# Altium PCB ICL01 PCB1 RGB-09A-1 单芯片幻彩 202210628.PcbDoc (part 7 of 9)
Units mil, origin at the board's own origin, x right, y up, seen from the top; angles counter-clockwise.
Board outline 17436.43 x 6581.89 mil, 2 copper layers (Top Layer, Bottom Layer), stack 65.792 mil thick; 425 components, 516 nets, 1625 pads, 2772 vias.
Unrouted connection lines stored in the file: 1.
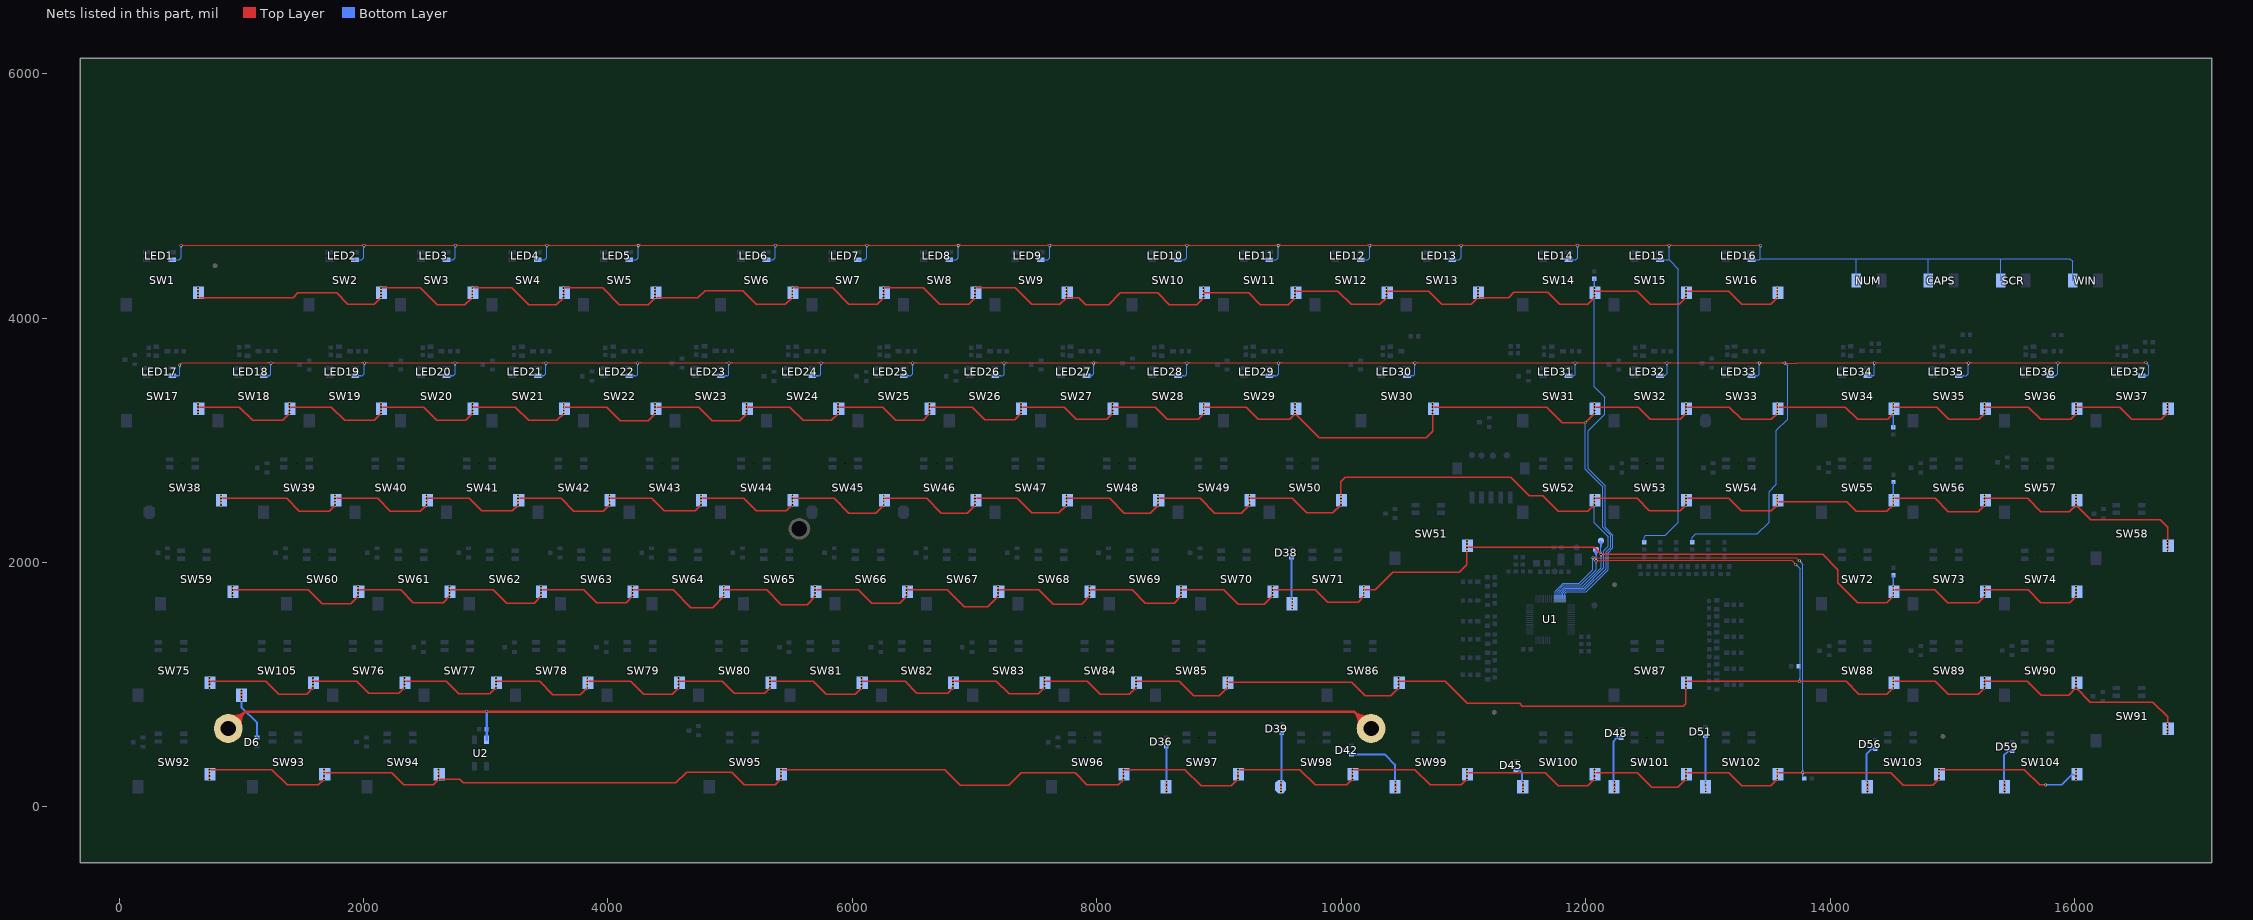
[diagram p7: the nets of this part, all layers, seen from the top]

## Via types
v1: diameter 23.62, hole 15.75, Top Layer to Bottom Layer, tented both sides, 2766 vias
v2: diameter 19.68, hole 11.81, Top Layer to Bottom Layer, tented both sides, 6 vias

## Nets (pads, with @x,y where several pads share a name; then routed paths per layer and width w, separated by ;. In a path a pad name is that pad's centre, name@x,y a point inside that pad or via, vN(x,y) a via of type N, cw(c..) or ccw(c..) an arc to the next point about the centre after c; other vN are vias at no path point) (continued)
NetSW97_2: D36.K2 SW97.2 | length 368.1
  Top Layer w15.75: v1(8568.65,206.14) v1(8568.65,179.47) v1(8568.65,152.81) 8568.65,128.11 v1@8570.62,126.14
  Bottom Layer w15.75: SW97.2@8569.36,206.14 D36.K2@8569.36,493.41
  other v1: 8568.65,126.14
NetSW98_2: D39.K2 SW98.2 | length 483.3
  Top Layer w15.75: v1(9505.66,126.14) v1(9505.66,152.81) v1(9505.66,179.47) v1(9505.66,206.14)
  Bottom Layer w15.75: SW98.2@9512.53,199.27 D39.K2@9512.53,602.59
NetSW99_2: D42.K2 SW99.2 | length 611.3
  Top Layer w15.75: v1@10440.7,126.14 10442.67,128.11 v1(10442.67,152.81) v1(10442.67,179.47) v1(10442.67,206.14)
  Bottom Layer w15.75: D42.K2@10083,427.67 10358.43,427.67 10439.44,346.66 SW99.2@10439.44,206.14
  other v1: 10442.67,126.14
NetSW100_2: D45.K2 SW100.2 | length 206.4
  Top Layer w15.75: v1@11485.98,133.03 v1(11485.98,152.81) v1(11485.98,179.47) v1(11485.98,206.14)
  Bottom Layer w15.75: D45.K2@11429.12,302.13 11458.31,302.13 11477.83,282.61 SW100.2@11477.83,206.14
  other v1: 11485.98,126.14
NetSW101_2: D48.K2 SW101.2 | length 476.8
  Top Layer w15.75: v1@12234.01,133.03 v1(12234.01,152.81) v1(12234.01,179.47) v1(12234.01,206.14)
  Bottom Layer w15.75: SW101.2@12225.86,206.14 12225.86,534.59 12255.71,564.45 D48.K2@12288.72,564.45
  other v1: 12234.01,126.14
NetSW102_2: D51.K2 SW102.2 | length 432.3
  Top Layer w15.75: v1@12982.04,133.03 v1(12982.04,152.81)
  Bottom Layer w15.75: D51.K2@12979.64,578.19 12980.78,577.06 SW102.2@12980.78,166.14
  other v1: 12982.04,126.14 12982.04,179.47 12982.04,206.14
NetSW103_2: D56.K2 SW103.2 | length 389.9
  Top Layer w15.75: v1@14304.87,131.06 v1(14304.87,152.81) v1(14304.87,179.47) v1(14304.87,206.14)
  Bottom Layer w15.75: SW103.2@14298.69,206.14 14298.69,435.24 14337.18,473.73 D56.K2@14368.42,473.73
  other v1: 14304.87,126.14
NetSW104_2: D59.K2 SW104.2 | length 374.4
  Top Layer w15.75: v1@15426.92,131.06 v1(15426.92,152.81) v1(15426.92,179.47) v1(15426.92,206.14)
  Bottom Layer w15.75: SW104.2@15420.74,206.14 15420.74,421.46 15455.29,456.01 D59.K2@15490.47,456.01
  other v1: 15426.92,126.14
NetSW105_2: D6.K1 SW105.2 | length 440.3
  Top Layer w15.75: v1(1001.72,874.17) v1(1001.72,900.84) v1(1001.72,927.5) v1(1001.72,954.17)
  Bottom Layer w15.75: SW105.2@1000.46,874.17 1000.46,816.55 1130,687.01 D6.K1@1130,567.5
NetSW106_2: D38.K2 SW71.2 | length 419.7
  Top Layer w15.75: v1(9599.17,1622.2) v1(9599.17,1648.87) v1(9599.17,1675.54) v1(9599.17,1702.2)
  Bottom Layer w15.75: SW71.2@9591.76,1702.2 D38.K2@9591.76,2041.94
NetU1_1: pad.10@893.77,641.74 pad.10@10244.15,641.74 R93.2 U2.1 | length 10848.5
  Top Layer w19.68: pad.10@909.65,708.78 ccw(c927.21,782.93) 981.08,729.05 ccw(c1034.96,675.17) pad.10@960.82,657.61 ; pad.10@914.19,727.94 ccw(c936.76,823.26) 1006.03,753.99 ccw(c1075.3,684.72) pad.10@979.97,662.15 ; pad.10@918.72,747.09 ccw(c946.31,863.6) 1030.98,778.94 ccw(c1115.64,694.27) pad.10@999.13,666.69 ; pad.10@924.48,672.44 1030.98,778.94 2869.76,778.94 10106.94,778.94 ; pad.10@10138.8,666.69 ccw(c10022.28,694.27) 10106.95,778.94 ; pad.10@10157.95,662.15 ccw(c10062.62,684.72) 10131.89,753.99 ccw(c10201.17,823.26) pad.10@10223.74,727.94 ; pad.10@10177.11,657.61 ccw(c10102.96,675.17) 10156.84,729.05 ccw(c10210.72,782.93) pad.10@10228.27,708.78 ; pad.10@10219.2,747.09 cw(c10191.61,863.6) 10106.95,778.94 ; pad.10@10244.15,641.74 10106.94,778.94
  Bottom Layer w19.68: U2.1@3007.4,549.28 v1(3007.4,780.58)
NetU4_16: 
NUMLED: 
NUNVCC: 
R0: RP1.2 SW1.1 SW2.1 SW3.1 SW4.1 SW5.1 SW6.1 SW7.1 SW8.1 SW9.1 SW10.1 SW11.1 SW12.1 SW13.1 SW14.1 SW15.1 SW16.1 U1.64 | length 18388
  Top Layer w11.81: v1@646.76,4247.08 646.76,4166.1 1424.47,4166.1 1464.4,4206.04 1779.9,4206.04 1872.81,4113.13 2087.88,4113.13 v1(2141.84,4167.08) v1(2141.84,4193.75) v1(2141.84,4220.42) v1(2141.84,4247.08) 2462.83,4247.08 2602.78,4107.13 2829.92,4107.13 v1(2889.87,4167.08) v1(2889.87,4193.75) v1(2889.87,4220.42) v1(2889.87,4247.08) 3213.68,4247.08 3352.41,4108.36 3579.18,4108.36 v1(3637.9,4167.08) v1(3637.9,4193.75) v1(3637.9,4220.42) v1(3637.9,4247.08) 3956.33,4247.08 4093.45,4109.97 4328.82,4109.97 v1(4385.94,4167.08) ; v1(4385.94,4247.08) v1(4385.94,4220.42) v1(4385.94,4193.75) v1(4385.94,4167.08) ; v1(7752.08,4247.08) v1(7752.08,4220.42) v1(7752.08,4193.75) v1(7752.08,4167.08) ; v1@8874.13,4205.18 9243.17,4205.18 9338.08,4110.27 9565.34,4110.27 v1(9622.16,4167.08) v1(9622.16,4193.75) v1(9622.16,4220.42) ; v1(8874.13,4220.42) v1(8874.13,4247.08) v1(8874.13,4193.75) v1(8874.13,4167.08) 8816.32,4109.28 8594.62,4109.28 8498.17,4205.73 8192.67,4205.73 8095.93,4108.98 7911.47,4108.98 7853.36,4167.08 v1(7752.08,4167.08) ; v1(9622.16,4247.08) v1(9622.16,4220.42) ; v1(10370.19,4247.08) v1(10370.19,4220.42) ; v1(11118.22,4247.08) v1(11118.22,4220.42) v1(11118.22,4193.75) v1(11118.22,4167.08) ; v1(12070.98,4247.08) v1(12070.98,4220.42) ; v1(12819.01,4247.08) v1(12819.01,4220.42) ; v1(13567.04,4247.08) v1(13567.04,4220.42) v1(13567.04,4193.75) v1(13567.04,4167.08) 13514.18,4114.23 13277.21,4114.23 13171.02,4220.42 v1(12819.01,4220.42) ; v1(4385.94,4167.08) 4736.18,4167.08 4794.36,4225.27 5101.16,4225.27 5215.68,4110.75 5451.65,4110.75 v1(5507.98,4167.08) v1(5507.98,4193.75) v1(5507.98,4220.42) v1(5507.98,4247.08) 5837.69,4247.08 5971.85,4112.93 6201.86,4112.93 v1(6256.02,4167.08) v1(6256.02,4193.75) v1(6256.02,4220.42) v1(6256.02,4247.08) 6579.59,4247.08 6712.99,4113.69 6950.65,4113.69 v1(7004.05,4167.08) v1(7004.05,4193.75) v1(7004.05,4220.42) v1(7004.05,4247.08) 7333.44,4247.08 7468.43,4112.1 7697.09,4112.1 v1(7752.08,4167.08) ; v1(9622.16,4220.42) 9972.01,4220.42 10081.03,4111.4 10314.51,4111.4 v1(10370.19,4167.08) v1(10370.19,4193.75) v1(10370.19,4220.42) ; v1(10370.19,4220.42) 10714.83,4220.42 10824.09,4111.16 11062.29,4111.16 v1(11118.22,4167.08) ; v1(11118.22,4167.08) 11369.62,4167.08 11413.08,4210.55 11690.57,4210.55 11789.37,4111.75 12015.64,4111.75 v1(12070.98,4167.08) v1(12070.98,4193.75) v1(12070.98,4220.42) ; v1(12070.98,4220.42) 12422.85,4220.42 12530.02,4113.25 12765.17,4113.25 v1(12819.01,4167.08) v1(12819.01,4193.75) v1(12819.01,4220.42)
  Bottom Layer w7.87: U1.64@11829.41,1703.16 11829.41,1745.9 11844.6,1761.1 12004.47,1761.1 12183.28,1939.9 12183.28,2080.65 12222.01,2119.38 12222.01,2223.5 12159.15,2286.36 12159.15,2628.76 12020.99,2766.91 12020.99,3077.41 12155.42,3211.84 12155.42,3353.22 12070.98,3437.66 v1(12070.98,4167.08)
  Bottom Layer w11.81: SW14.1@12069.95,4247.08 RP1.2@12069.95,4319.71
  other v1: 645.78,4167.08 645.78,4193.75 645.78,4220.42 645.78,4247.08
R1: RP2.2 SW17.1 SW18.1 SW19.1 SW20.1 SW21.1 SW22.1 SW23.1 SW24.1 SW25.1 SW26.1 SW27.1 SW28.1 SW29.1 SW30.1 SW31.1 SW32.1 SW33.1 SW34.1 SW35.1 SW36.1 SW37.1 U1.63 | length 20964.6
  Top Layer w11.81: v1(646.76,3218.27) v1(646.76,3244.93) ; 646.76,3257.34 cw(c661.02,3257.34) v1@650.94,3267.42 ; v1(646.76,3298.27) v1(646.76,3271.6) 983.67,3271.6 1092.39,3162.87 1339.4,3162.87 v1(1394.8,3218.27) v1(1394.8,3244.93) ; 1394.79,3257.34 cw(c1409.05,3257.34) v1@1398.97,3267.42 ; v1(1394.8,3298.27) v1(1394.8,3271.6) 1737.37,3271.6 1845.52,3163.45 2088.01,3163.45 v1(2142.83,3218.27) v1(2142.83,3244.93) ; 2142.83,3257.34 cw(c2157.08,3257.34) v1@2147,3267.42 ; v1(2142.83,3298.27) v1(2142.83,3271.6) 2491.96,3271.6 2599.88,3163.68 2836.27,3163.68 v1(2890.86,3218.27) v1(2890.86,3244.93) ; 2890.86,3257.34 cw(c2905.12,3257.34) v1@2895.03,3267.42 ; v1(2890.86,3298.27) v1(2890.86,3271.6) 3242.26,3271.6 3351.83,3162.04 3582.66,3162.04 v1(3638.89,3218.27) v1(3638.89,3244.93) ; 3638.89,3257.34 cw(c3653.15,3257.34) 3643.06,3267.42 cw(c3653.15,3257.34) 3653.15,3271.6 cw(c3653.15,3285.86) 3643.06,3275.78 cw(c3653.15,3285.86) 3638.89,3285.86 ; v1(3638.89,3271.6) 3990.2,3271.6 4102.23,3159.57 4328.23,3159.57 v1(4386.92,3218.27) v1(4386.92,3244.93) v1(4386.92,3271.6) ; v1(4386.92,3298.27) v1(4386.92,3271.6) ; v1(5134.95,3218.27) 5077.98,3161.29 4855.02,3161.29 4744.72,3271.6 v1(4386.92,3271.6) ; 5134.95,3230.68 cw(c5149.21,3230.68) v1@5139.13,3240.76 ; v1(5134.95,3244.93) v1(5134.95,3271.6) ; v1(5134.95,3298.27) v1(5134.95,3271.6) ; v1(5882.98,3218.27) 5827.64,3162.93 5596.47,3162.93 5487.8,3271.6 v1(5134.95,3271.6) ; 5882.98,3230.68 cw(c5897.24,3230.68) v1@5887.16,3240.76 ; v1(5882.98,3244.93) v1(5882.98,3271.6) ; v1(5882.98,3298.27) v1(5882.98,3271.6) ; v1(6631.02,3218.27) 6578.08,3165.34 6354.82,3165.34 6248.56,3271.6 v1(5882.98,3271.6) ; 6631.01,3230.68 cw(c6645.27,3230.68) v1@6635.19,3240.76 ; v1(6631.02,3244.93) v1(6631.02,3271.6) ; v1(6631.02,3298.27) v1(6631.02,3271.6) ; v1(7379.05,3218.27) 7328.65,3167.87 7085.03,3167.87 6981.3,3271.6 v1(6631.02,3271.6) ; 7379.05,3230.68 cw(c7393.3,3230.68) v1@7383.22,3240.76 ; v1(7379.05,3244.93) v1(7379.05,3271.6) ; v1(7379.05,3298.27) v1(7379.05,3271.6) ; v1(8127.08,3218.27) 8081.84,3173.03 7831.97,3173.03 7733.41,3271.6 v1(7379.05,3271.6) ; 8127.08,3230.68 cw(c8141.34,3230.68) v1@8131.25,3240.76 ; v1(8127.08,3244.93) v1(8127.08,3271.6) ; v1(8127.08,3298.27) v1(8127.08,3271.6) ; v1(8875.11,3218.27) 8830.11,3173.26 8576.17,3173.26 8477.83,3271.6 v1(8127.08,3271.6) ; 8875.11,3230.68 cw(c8889.37,3230.68) v1@8879.29,3240.76 ; v1(8875.11,3244.93) v1(8875.11,3271.6) ; v1(8875.11,3298.27) v1(8875.11,3271.6) ; v1(9623.14,3298.27) v1(9623.14,3271.6) v1(9623.14,3244.93) v1(9623.14,3218.27) ; v1(10748.14,3298.27) v1(10748.14,3271.6) ; v1(12070.98,3218.27) v1(11997.67,3144.96) 11808.82,3144.96 11682.19,3271.6 v1(10748.14,3271.6) ; v1@12070.98,3225.16 v1(12070.98,3244.93) v1(12070.98,3271.6) ; v1(12070.98,3298.27) v1(12070.98,3271.6) ; v1(12819.01,3298.27) v1(12819.01,3271.6) ; v1(13567.04,3298.27) v1(13567.04,3271.6) ; v1(14515.86,3218.27) 14470.62,3173.03 14223.94,3173.03 14125.38,3271.6 v1(13567.04,3271.6) ; v1(14515.86,3298.27) v1(14515.86,3271.6) 14872.58,3271.6 14972.14,3172.04 15217.66,3172.04 v1(15263.89,3218.27) ; v1@15263.89,3223.19 v1(15263.89,3244.93) v1(15263.89,3271.6) ; v1(15263.89,3298.27) v1(15263.89,3271.6) ; v1(16011.92,3218.27) 15966.61,3172.95 15721.23,3172.95 15622.58,3271.6 v1(15263.89,3271.6) ; v1@16011.92,3223.19 v1(16011.92,3244.93) v1(16011.92,3271.6) ; v1(16011.92,3298.27) v1(16011.92,3271.6) ; v1@16755.03,3218.27 16709.49,3172.72 16467.43,3172.72 16368.56,3271.6 v1(16011.92,3271.6) ; v1@16759.21,3294.09 16759.95,3293.34 v1(16759.95,3271.6) v1(16759.95,3244.93) v1(16759.95,3218.27) ; v1(8875.11,3271.6) 9224.25,3271.6 9322.7,3173.14 9578.02,3173.14 v1(9623.14,3218.27) ; v1(9623.14,3218.27) 9820.57,3020.83 10696.58,3020.83 10748.14,3072.39 v1(10748.14,3218.27) v1(10748.14,3244.93) v1(10748.14,3271.6) ; v1(12070.98,3271.6) 12428.66,3271.6 12527.22,3173.03 12773.77,3173.03 v1(12819.01,3218.27) v1(12819.01,3244.93) v1(12819.01,3271.6) ; v1(12819.01,3271.6) 13176.09,3271.6 13277.74,3169.95 13518.73,3169.95 v1(13567.04,3218.27) v1(13567.04,3244.93) v1(13567.04,3271.6)
  Bottom Layer w7.87: U1.63@11813.66,1703.16 11813.66,1749.77 11838.86,1774.97 11992.76,1774.97 12167.4,1949.62 12167.4,2089.09 12204.38,2126.07 12204.38,2221.51 12139.65,2286.24 12139.65,2619.2 11997.67,2761.18 v1(11997.67,3144.96)
  Bottom Layer w11.81: RP2.2@14516.11,3106.97 14516.11,3252.65 SW34.1@14521.72,3258.27
  other v1: 14515.86,3244.93 3638.89,3298.27 16759.95,3298.27
R2: RP3.2 SW38.1 SW39.1 SW40.1 SW41.1 SW42.1 SW43.1 SW44.1 SW45.1 SW46.1 SW47.1 SW48.1 SW49.1 SW50.1 SW52.1 SW53.1 SW54.1 SW55.1 SW56.1 SW57.1 SW58.1 U1.62 | length 20184.6
  Top Layer w11.81: v1(833.77,2550.23) v1(833.77,2523.57) ; v1(1768.81,2496.9) v1(1768.81,2470.23) 1719.77,2421.19 1473.36,2421.19 1370.98,2523.57 v1(833.77,2523.57) ; 1768.81,2509.31 cw(c1783.07,2509.31) v1@1772.99,2519.39 ; v1(1768.81,2550.23) v1(1768.81,2523.57) 2116.03,2523.57 2219.63,2419.96 2466.57,2419.96 v1(2516.84,2470.23) v1(2516.84,2496.9) ; 2516.84,2509.31 cw(c2531.1,2509.31) v1@2521.02,2519.39 ; v1(2516.84,2550.23) v1(2516.84,2523.57) 2865.98,2523.57 2967.32,2422.22 3216.86,2422.22 v1(3264.87,2470.23) v1(3264.87,2496.9) ; 3264.87,2509.31 cw(c3279.13,2509.31) v1@3269.05,2519.39 ; v1(3264.87,2550.23) v1(3264.87,2523.57) 3616.32,2523.57 3722.23,2417.66 3960.33,2417.66 v1(4012.91,2470.23) ; 4012.9,2482.64 cw(c4027.16,2482.64) v1@4017.08,2492.72 ; v1(4012.91,2496.9) v1(4012.91,2523.57) ; v1(4012.91,2550.23) v1(4012.91,2523.57) ; v1(4760.94,2470.23) 4714,2423.29 4460.89,2423.29 4360.62,2523.57 v1(4012.91,2523.57) ; 4760.94,2482.64 cw(c4775.19,2482.64) v1@4765.11,2492.72 ; v1(4760.94,2496.9) v1(4760.94,2523.57) ; v1(4760.94,2550.23) v1(4760.94,2523.57) ; v1(5508.97,2470.23) 5460.44,2421.7 5215.02,2421.7 5113.16,2523.57 v1(4760.94,2523.57) ; 5508.97,2482.64 cw(c5523.23,2482.64) v1@5513.14,2492.72 ; v1(5508.97,2496.9) v1(5508.97,2523.57) ; v1(5508.97,2550.23) v1(5508.97,2523.57) ; v1(6257,2470.23) 6190.99,2404.23 5972.05,2404.23 5852.7,2523.57 v1(5508.97,2523.57) ; 6257,2482.64 cw(c6271.26,2482.64) v1@6261.17,2492.72 ; v1(6257,2496.9) v1(6257,2523.57) ; v1(6257,2550.23) v1(6257,2523.57) ; v1(7005.03,2470.23) 6938.39,2403.6 6728.19,2403.6 6608.22,2523.57 v1(6257,2523.57) ; 7005.03,2482.64 cw(c7019.29,2482.64) v1@7009.21,2492.72 ; v1(7005.03,2496.9) v1(7005.03,2523.57) ; v1(7005.03,2550.23) v1(7005.03,2523.57) ; v1(7753.06,2470.23) 7688.11,2405.28 7469.29,2405.28 7351,2523.57 v1(7005.03,2523.57) ; 7753.06,2482.64 cw(c7767.32,2482.64) v1@7757.24,2492.72 ; v1(7753.06,2496.9) v1(7753.06,2523.57) ; v1(7753.06,2550.23) v1(7753.06,2523.57) ; v1(8501.09,2550.23) v1(8501.09,2523.57) ; v1(9249.12,2470.23) 9183.63,2404.74 8965.76,2404.74 8846.92,2523.57 v1(8501.09,2523.57) ; 9249.12,2482.64 cw(c9263.38,2482.64) v1@9253.3,2492.72 ; v1(9249.12,2496.9) v1(9249.12,2523.57) ; v1(9249.12,2550.23) v1(9249.12,2523.57) ; v1(12070.98,2550.23) v1(12070.98,2523.57) ; v1(12819.01,2550.23) v1(12819.01,2523.57) ; v1(13567.04,2550.23) v1(13567.04,2523.57) v1(13567.04,2496.9) ; v1(14515.86,2470.23) 14463.95,2418.32 14215.17,2418.32 14136.59,2496.9 v1(13567.04,2496.9) ; v1@14515.86,2475.16 v1(14515.86,2496.9) v1(14515.86,2523.57) ; v1(14515.86,2550.23) v1(14515.86,2523.57) ; v1(15263.89,2470.23) 15209.83,2416.17 14965.73,2416.17 14858.33,2523.57 v1(14515.86,2523.57) ; v1@15263.89,2475.16 v1(15263.89,2496.9) v1(15263.89,2523.57) ; v1(15263.89,2550.23) v1(15263.89,2523.57) ; v1(16011.92,2550.23) v1(16011.92,2523.57) v1(16011.92,2496.9) v1(16011.92,2470.23) ; v1(16759.95,2096.22) v1(16759.95,2122.89) v1(16759.95,2149.55) v1(16759.95,2176.22) 16759.95,2288.9 16700.3,2348.55 16133.6,2348.55 v1(16011.92,2470.23) ; v1(833.77,2523.57) v1(833.77,2496.9) v1(833.77,2470.23) v1(833.77,2523.57) ; v1(7753.06,2523.57) 8107.5,2523.57 8226.22,2404.85 8435.71,2404.85 v1(8501.09,2470.23) v1(8501.09,2496.9) v1(8501.09,2523.57) ; v1(9249.12,2523.57) 9597.8,2523.57 9716.41,2404.96 9931.88,2404.96 v1(9997.16,2470.23) v1(9997.16,2496.9) v1(9997.16,2523.57) v1(9997.16,2550.23) 9997.16,2660.22 10034.05,2697.12 11387.74,2697.12 11539.71,2545.14 11649.77,2545.14 11777.07,2417.85 12018.59,2417.85 v1(12070.98,2470.23) v1(12070.98,2496.9) v1(12070.98,2523.57) ; v1(12070.98,2523.57) 12420.47,2523.57 12520.57,2423.46 12772.24,2423.46 v1(12819.01,2470.23) v1(12819.01,2496.9) v1(12819.01,2523.57) ; v1(12819.01,2523.57) 13171.36,2523.57 13273.29,2421.63 13518.44,2421.63 v1(13567.04,2470.23) v1(13567.04,2496.9) ; v1(15263.89,2523.57) 15615.08,2523.57 15723.97,2414.68 15956.36,2414.68 v1(16011.92,2470.23)
  Bottom Layer w7.87: U1.62@11797.91,1703.16 11797.91,1753.65 11833.11,1788.84 11982.02,1788.84 12149.5,1956.32 12149.5,2096.18 12186.04,2132.72 12186.04,2210.56 12069.65,2326.95 SW52.1@12069.65,2470.23
  Bottom Layer w11.81: SW55.1@14517.4,2550.23 RP3.2@14517.4,2657.9
R3: pad.8 RP4.2 SW51.1 SW59.1 SW60.1 SW61.1 SW62.1 SW63.1 SW64.1 SW65.1 SW66.1 SW67.1 SW68.1 SW69.1 SW70.1 SW71.1 SW72.1 SW73.1 SW74.1 U1.61 | length 18778.5
  Top Layer w11.81: v1(927.28,1722.2) v1(927.28,1748.87) ; 927.28,1761.28 cw(c941.53,1761.28) v1@931.45,1771.36 ; v1(927.28,1802.2) v1(927.28,1775.54) 1549.74,1775.54 1660.97,1664.31 1897.92,1664.31 v1(1955.82,1722.2) v1(1955.82,1748.87) ; 1955.82,1761.28 cw(c1970.08,1761.28) v1@1959.99,1771.36 ; v1(1955.82,1802.2) v1(1955.82,1775.54) 2304.44,1775.54 2408.16,1671.82 2653.47,1671.82 v1(2703.85,1722.2) v1(2703.85,1748.87) ; 2703.85,1761.28 cw(c2718.11,1761.28) v1@2708.03,1771.36 ; v1(2703.85,1802.2) v1(2703.85,1775.54) 3063.36,1775.54 3170.77,1668.12 3397.8,1668.12 v1(3451.88,1722.2) v1(3451.88,1748.87) ; 3451.88,1761.28 cw(c3466.14,1761.28) v1@3456.06,1771.36 ; v1(3451.88,1802.2) v1(3451.88,1775.54) 3803.56,1775.54 3907.21,1671.89 4149.6,1671.89 v1(4199.91,1722.2) v1(4199.91,1748.87) ; 4199.91,1761.28 cw(c4214.17,1761.28) 4204.09,1771.36 cw(c4214.17,1761.28) 4214.17,1775.54 cw(c4214.17,1789.79) 4204.09,1779.71 cw(c4214.17,1789.79) 4199.91,1789.79 ; v1(4199.91,1775.54) 4534.1,1775.54 4679.58,1630.05 4855.8,1630.05 v1(4947.94,1722.2) v1(4947.94,1748.87) ; 4947.94,1761.28 cw(c4962.2,1761.28) v1@4952.12,1771.36 ; v1(4947.94,1802.2) v1(4947.94,1775.54) 5299.82,1775.54 5419.38,1655.98 5629.75,1655.98 v1(5695.98,1722.2) v1(5695.98,1748.87) ; 5695.98,1761.28 cw(c5710.23,1761.28) v1@5700.15,1771.36 ; v1(5695.98,1802.2) v1(5695.98,1775.54) 6046.93,1775.54 6157.8,1664.66 6386.46,1664.66 v1(6444.01,1722.2) v1(6444.01,1748.87) ; 6444.01,1761.28 cw(c6458.26,1761.28) v1@6448.18,1771.36 ; v1(6444.01,1802.2) v1(6444.01,1775.54) 6777.3,1775.54 6915.35,1637.49 7107.33,1637.49 v1(7192.04,1722.2) v1(7192.04,1748.87) ; 7192.04,1761.28 cw(c7206.3,1761.28) v1@7196.21,1771.36 ; v1(7192.04,1802.2) v1(7192.04,1775.54) 7526.3,1775.54 7643.78,1658.06 7875.92,1658.06 v1(7940.07,1722.2) v1(7940.07,1748.87) ; 7940.07,1761.28 cw(c7954.33,1761.28) v1@7944.25,1771.36 ; v1(7940.07,1802.2) v1(7940.07,1775.54) 8288.45,1775.54 8395.56,1668.43 8634.33,1668.43 v1(8688.1,1722.2) v1(8688.1,1748.87) ; 8688.1,1761.28 cw(c8702.36,1761.28) v1@8692.28,1771.36 ; v1(8688.1,1802.2) v1(8688.1,1775.54) 9037.04,1775.54 9155.43,1657.14 9371.07,1657.14 v1(9436.13,1722.2) v1(9436.13,1748.87) ; 9436.13,1761.28 cw(c9450.39,1761.28) v1@9440.31,1771.36 ; v1(9436.13,1802.2) v1(9436.13,1775.54) 9788.94,1775.54 9888.43,1676.05 10138.01,1676.05 v1(10184.17,1722.2) v1(10184.17,1748.87) v1(10184.17,1775.54) ; v1(10184.17,1802.2) v1(10184.17,1775.54) ; v1@11027.67,2176.16 v1(11027.67,2122.89) ; v1@12119.86,2065.36 ccw(c12105.61,2065.36) 12115.69,2075.44 ccw(c12125.77,2085.52) v1@12125.77,2071.27 ; v1@12129.95,2061.19 cw(c12140.03,2051.1) 12140.03,2065.36 cw(c12140.03,2079.62) v1@12129.95,2069.54 ; v1(14515.86,1802.2) v1(14515.86,1775.54) ; v1(15263.89,1802.2) v1(15263.89,1775.54) ; v1(16011.92,1802.2) v1(16011.92,1775.54) v1(16011.92,1748.87) v1(16011.92,1722.2) 15961.96,1672.24 15724.95,1672.24 15621.66,1775.54 v1(15263.89,1775.54) ; v1(10184.17,1775.54) 10278.44,1775.54 10422.3,1919.39 10965.18,1919.39 11027.67,1981.88 v1(11027.67,2096.22) v1(11027.67,2122.89) ; v1(11027.67,2122.89) 12068.25,2122.89 v1(12125.77,2065.36) 13938.66,2065.36 14062.98,1941.05 14062.98,1833.68 14225.85,1670.8 14464.46,1670.8 v1(14515.86,1722.2) v1(14515.86,1748.87) v1(14515.86,1775.54) ; v1(14515.86,1775.54) 14857.6,1775.54 14962.21,1670.93 15212.61,1670.93 v1(15263.89,1722.2) v1(15263.89,1748.87) v1(15263.89,1775.54)
  Bottom Layer w7.87: U1.61@11782.16,1703.16 11782.16,1757.52 11827.36,1802.72 11971.29,1802.72 12125.77,1957.2 v1(12125.77,2065.36) ; pad.8@12109.65,2162.26 cw(c12072.69,2125.29) 12124.96,2125.29 cw(c12177.24,2125.29) pad.8@12140.27,2162.26 ; pad.8@12115.22,2167.82 cw(c12091.7,2144.3) 12124.96,2144.3 cw(c12158.23,2144.3) pad.8@12134.71,2167.82 ; v1@12120.2,2059.79 cw(c12106.76,2046.35) 12125.77,2046.35 cw(c12144.78,2046.35) v1@12131.34,2059.79 ; v1@12120.2,2070.93 ccw(c12108.71,2082.42) 12124.96,2082.42 ; v1@12124.96,2065.36 pad.8@12124.96,2177.57 ; 12124.96,2086.32 ccw(c12146.73,2086.32) v1@12131.34,2070.93
  Bottom Layer w11.81: SW72.1@14516.8,1802.2 RP4.2@14516.8,1895.5
  other v1: 4199.91,1802.2 11027.67,2149.55 11027.67,2176.22
R4: pad.7 RP5.2 SW75.1 SW76.1 SW77.1 SW78.1 SW79.1 SW80.1 SW81.1 SW82.1 SW83.1 SW84.1 SW85.1 SW86.1 SW87.1 SW88.1 SW89.1 SW90.1 SW91.1 SW105.1 U1.60 | length 22545.4
  Top Layer w7.87: v1(12085.25,2013.76) 12116.38,2013.76 12119.76,2017.13 13684.04,2017.13 v1(13717.63,1983.55) ; v1@12090.82,2008.19 cw(c12104.26,1994.75) 12104.26,2013.76 cw(c12104.26,2032.77) v1@12090.82,2019.32 ; v1@13709.76,1983.55 ccw(c13690.75,1983.55) 13704.19,1996.99 ccw(c13717.63,2010.43) v1@13717.63,1991.42
  Top Layer w11.81: v1@736.09,996.85 cw(c726.01,986.76) 740.27,986.76 ; v1@740.27,1001.02 v1(740.27,1027.5) 1200.82,1027.5 1306.22,922.1 1534.66,922.1 v1(1586.72,974.17) ; 740.27,1015.28 ccw(c754.52,1015.28) v1@744.44,1005.2 ; v1@740.27,1027.69 v1@740.27,1054.35 ; v1@1585.98,978.35 1586.72,979.09 v1(1586.72,1000.84) v1(1586.72,1027.5) ; v1(1586.72,1054.17) v1(1586.72,1027.5) ; v1@2332.29,976.63 2334.76,979.09 v1(2334.76,1000.84) v1(2334.76,1027.5) ; v1(2334.76,974.17) 2289.6,929.01 2189.05,929.01 2188.32,929.74 2175.17,929.74 2174.44,929.01 2041.56,929.01 1943.07,1027.5 v1(1586.72,1027.5) ; v1(2334.76,1054.17) v1(2334.76,1027.5) ; v1(3082.79,1054.17) v1(3082.79,1027.5) ; v1(3830.82,1054.17) v1(3830.82,1027.5) ; v1(4578.85,1054.17) v1(4578.85,1027.5) ; v1@5326.88,1000.4 v1(5326.88,974.17) 5281.72,929.01 5181.17,929.01 5180.45,929.74 5167.29,929.74 5166.57,929.01 5035.17,929.01 4936.68,1027.5 v1(4578.85,1027.5) ; v1(5326.88,1000.84) v1(5326.88,1027.5) ; v1(5326.88,1054.17) v1(5326.88,1027.5) ; v1(6074.91,1054.17) v1(6074.91,1027.5) ; v1(6822.94,1054.17) v1(6822.94,1027.5) ; v1(7570.98,1054.17) v1(7570.98,1027.5) ; v1(8319.01,1054.17) v1(8319.01,1027.5) ; v1(9067.04,1054.17) v1(9067.04,1027.5) ; v1(10468.61,1054.17) v1(10468.61,1027.5) ; v1(12819.01,1000.84) v1(12819.01,1027.5) ; v1(12819.01,1054.17) v1(12819.01,1027.5) ; 13733.75,1027.5 ccw(c13733.75,1042.42) v1@13744.3,1031.87 ; 13734.68,1027.5 cw(c13734.68,1013.9) v1@13744.3,1023.52 ; v1@13752.65,1023.52 cw(c13762.27,1013.9) 13762.27,1027.5 ; v1@13752.65,1031.87 ccw(c13763.19,1042.42) 13763.19,1027.5 ; v1(14515.86,1054.17) v1(14515.86,1027.5) ; v1(15263.89,1054.17) v1(15263.89,1027.5) ; v1(16011.92,1054.17) v1(16011.92,1027.5) v1(16011.92,1000.84) v1(16011.92,974.17) ; v1(16759.95,600.16) v1(16759.95,626.82) v1(16759.95,653.49) v1(16759.95,680.16) 16759.95,735.95 16638.74,857.16 16128.93,857.16 v1(16011.92,974.17) ; v1(2334.76,1027.5) 2677.26,1027.5 2780.75,924.01 3032.62,924.01 v1(3082.79,974.17) v1(3082.79,1000.84) v1(3082.79,1027.5) ; v1(3082.79,1027.5) 3440.35,1027.5 3549.23,918.63 3775.28,918.63 v1(3830.82,974.17) v1(3830.82,1000.84) v1(3830.82,1027.5) ; v1(3830.82,1027.5) 4188.75,1027.5 4293.42,922.83 4527.51,922.83 v1(4578.85,974.17) v1(4578.85,1000.84) v1(4578.85,1027.5) ; v1(5326.88,1027.5) 5681.36,1027.5 5786.3,922.57 6023.31,922.57 v1(6074.91,974.17) v1(6074.91,1000.84) v1(6074.91,1027.5) ; v1(6074.91,1027.5) 6432.23,1027.5 6527.8,931.93 6780.71,931.93 v1(6822.94,974.17) v1(6822.94,1000.84) v1(6822.94,1027.5) ; v1(6822.94,1027.5) 7179.01,1027.5 7281.78,924.73 7521.54,924.73 v1(7570.98,974.17) v1(7570.98,1000.84) v1(7570.98,1027.5) ; v1(7570.98,1027.5) 7922.67,1027.5 8028.16,922.01 8266.85,922.01 v1(8319.01,974.17) v1(8319.01,1000.84) v1(8319.01,1027.5) ; v1(8319.01,1027.5) 8673.87,1027.5 8792.47,908.9 9001.76,908.9 v1(9067.04,974.17) ; v1(9067.04,974.17) v1(9067.04,1027.5) ; v1(9067.04,974.17) v1(9067.04,1000.84) v1(9067.04,1027.5) ; v1(9067.04,1027.5) 9072.42,1022.12 10087.32,1022.12 10198.06,911.38 10405.82,911.38 v1(10468.61,974.17) ; v1(10468.61,974.17) v1(10468.61,1027.5) ; v1(10468.61,974.17) v1(10468.61,1000.84) v1(10468.61,1027.5) ; v1(10468.61,1027.5) 10851.28,1027.5 11032.2,846.59 11460.24,846.59 11482.15,824.68 12797.52,824.68 12819.01,846.16 v1(12819.01,974.17) v1(12819.01,1027.5) ; v1(12819.01,1027.5) 14130.92,1027.5 14235.43,923 14235.43,921.93 14235.72,921.64 14463.33,921.64 v1(14515.86,974.17) v1(14515.86,1000.84) v1(14515.86,1027.5) ; v1(14515.86,1027.5) 14861.7,1027.5 14965.71,923.5 15213.21,923.5 v1(15263.89,974.17) v1(15263.89,1000.84) v1(15263.89,1027.5) ; v1(15263.89,1027.5) 15612.34,1027.5 15725.18,914.66 15951.07,914.66 16010.59,974.17 v1(16011.92,974.17)
  Bottom Layer w7.87: U1.60@11766.42,1703.16 11766.42,1761.39 11821.62,1816.59 11959.57,1816.59 12084.78,1941.8 pad.7@12084.78,2102.76 ; pad.7@12069.47,2087.45 cw(c12032.51,2050.49) 12084.78,2050.49 cw(c12137.06,2050.49) pad.7@12100.09,2087.45 ; pad.7@12075.04,2093.02 cw(c12051.52,2069.5) 12084.78,2069.5 cw(c12118.05,2069.5) pad.7@12094.53,2093.02 ; v1@12079.69,2008.19 cw(c12067.38,1995.88) 12084.78,1995.88 ; v1@12079.69,2019.32 ccw(c12067.38,2031.63) 12084.78,2031.63 ; 12084.78,1993.61 cw(c12105.4,1993.61) v1@12090.82,2008.19 ; 12084.78,2033.9 ccw(c12105.4,2033.9) v1@12090.82,2019.32 ; v1@13717.63,1975.67 cw(c13717.63,1956.66) 13731.07,1970.11 cw(c13744.52,1983.55) v1@13725.51,1983.55 ; v1(13717.63,1983.55) 13753.62,1947.56 v1@13753.62,1026.3 ; v1@13742.9,1033.26 ccw(c13717.03,1059.14) 13753.62,1059.14 ; v1(13748.47,1027.7) ccw(c13736.04,1040.13) 13753.62,1040.13
  other v1: 740.27,974.17 740.27,1000.84 740.27,1054.17
R5: RP6.2 SW92.1 SW93.1 SW94.1 SW95.1 SW96.1 SW97.1 SW98.1 SW99.1 SW100.1 SW101.1 SW102.1 SW103.1 SW104.1 U1.59 | length 21628.5
  Top Layer w7.87: v1(12059.54,2038.79) 13723.52,2038.79 v1(13747.86,2014.45) ; v1@12065.11,2033.22 cw(c12078.55,2019.78) 12078.55,2038.79 cw(c12078.55,2057.8) v1@12065.11,2044.35 ; v1@13739.99,2014.45 ccw(c13720.98,2014.45) 13734.42,2027.89 ccw(c13747.86,2041.33) v1@13747.86,2022.32
  Top Layer w11.81: v1(740.27,226.14) v1(740.27,252.81) v1(740.27,279.47) v1(740.27,306.14) 1249.71,306.14 1374.94,180.91 1632.04,180.91 v1(1677.27,226.14) v1(1677.27,252.81) v1(1677.27,279.47) ; v1(1677.27,306.14) v1(1677.27,279.47) ; v1(2614.28,306.14) v1(2614.28,279.47) v1(2614.28,252.81) v1(2614.28,226.14) ; v1@8216.65,230.08 v1(8216.65,252.81) v1(8216.65,279.47) v1(8216.65,306.14) 8720.54,306.14 8853.48,173.2 9100.71,173.2 v1(9153.65,226.14) v1(9153.65,252.81) v1(9153.65,279.47) v1(9153.65,306.14) 9661.92,306.14 9787.16,180.91 10045.43,180.91 v1(10090.66,226.14) v1(10090.66,252.81) v1(10090.66,279.47) v1(10090.66,306.14) 10602.71,306.14 10727.94,180.91 10982.43,180.91 v1(11027.67,226.14) v1(11027.67,279.47) ; v1@8218.61,224.17 8175.35,180.91 7918.88,180.91 7821.87,277.92 7381.82,277.92 7281.43,177.52 6884.63,177.52 6756.01,306.14 v1(5415.46,306.14) v1(5415.46,279.47) v1(5415.46,252.81) v1(5415.46,226.14) 5370.23,180.91 5115.74,180.91 5012.32,284.32 4643.01,284.32 4555.25,196.56 2816.9,196.56 2787.32,226.14 v1(2614.28,226.14) ; v1@9151.45,275.3 cw(c9141.36,265.22) 9155.62,265.22 ; v1@9155.62,226.14 v1@9155.62,252.81 ; v1(11027.67,252.81) v1(11027.67,279.47) ; v1(11027.67,306.14) v1(11027.67,279.47) ; v1(12070.98,306.14) v1(12070.98,279.47) ; v1(12819.01,306.14) v1(12819.01,279.47) ; v1(13567.04,306.14) v1(13567.04,279.47) ; 13759.85,279.47 ccw(c13759.85,296) v1@13771.54,284.32 ; 13763.06,279.47 cw(c13763.06,267.49) v1@13771.54,275.96 ; v1@13779.89,275.96 cw(c13788.36,267.49) 13788.36,279.47 ; v1@13779.89,284.32 ccw(c13791.58,296) 13791.58,279.47 ; v1@15759.88,176.73 ccw(c15749.8,166.65) 15749.8,180.91 ccw(c15749.8,195.16) v1@15759.88,185.08 ; v1(15764.06,180.91) 15714.06,180.91 15588.83,306.14 v1(14889.87,306.14) v1(14889.87,279.47) v1(14889.87,252.81) v1(14889.87,226.14) 14840.31,176.57 14599.32,176.57 14496.42,279.47 v1(13567.04,279.47) ; v1@16011.92,231.06 v1(16011.92,252.81) v1(16011.92,279.47) v1(16011.92,306.14) ; v1(1677.27,279.47) 2229.64,279.47 2328.21,180.91 2569.05,180.91 v1(2614.28,226.14) ; v1(11027.67,279.47) 11668.98,279.47 11775.28,173.17 12018.01,173.17 v1(12070.98,226.14) v1(12070.98,252.81) v1(12070.98,279.47) ; v1(12070.98,279.47) 12423.34,279.47 12541.35,161.46 12754.33,161.46 v1(12819.01,226.14) v1(12819.01,252.81) v1(12819.01,279.47) ; v1(12819.01,279.47) 13169,279.47 13276.44,172.04 13512.93,172.04 v1(13567.04,226.14) v1(13567.04,252.81) v1(13567.04,279.47)
  Bottom Layer w7.87: U1.59@11750.67,1703.16 11750.67,1765.26 11815.87,1830.47 11948.84,1830.47 12059.54,1941.17 v1(12059.54,2038.79) ; v1@12053.98,2033.22 cw(c12040.53,2019.78) 12059.54,2019.78 cw(c12078.55,2019.78) v1@12065.11,2033.22 ; v1@13747.86,2006.57 cw(c13747.86,1987.56) 13761.3,2001.01 cw(c13774.74,2014.45) v1@13755.73,2014.45 ; v1(13747.86,2014.45) 13775.27,1987.04 RP6.2@13775.27,241.73 ; v1@13770.15,274.57 cw(c13757.77,262.19) 13775.27,262.19 ; v1@13770.15,285.71 ccw(c13757.77,298.09) 13775.27,298.09 ; 13775.27,260.07 cw(c13795.78,260.07) v1@13781.28,274.57 ; 13775.27,300.21 ccw(c13795.78,300.21) v1@13781.28,285.71
  Bottom Layer w11.81: v1(15764.06,180.91) 15894.76,180.91 15979.99,266.14 cw(c15979.99,243.47) SW104.1@16001.42,250.88 ; v1@15768.24,176.73 cw(c15778.32,166.65) 15778.32,180.91 cw(c15778.32,195.16) v1@15768.24,185.08
  other v1: 8216.65,226.14 16011.92,226.14 13775.71,280.14
RED0: CAPS.2 LED1.R LED2.R LED3.R LED4.R LED5.R LED6.R LED7.R LED8.R LED9.R LED10.R LED11.R LED12.R LED13.R LED14.R LED15.R LED16.R NUM.2 RR1.2 SCR.2 WIN.2 | length 23023.4
  Top Layer w7.87: v1(508.3,4594.23) v1(3500.42,4594.23) v1(8736.64,4594.23) v1(10232.71,4594.23) v1(10980.74,4594.23) v1(11933.49,4594.23) v1(13429.56,4594.23) ; v1@513.86,4588.66 cw(c527.31,4575.22) 527.31,4594.23 cw(c527.31,4613.24) v1@513.86,4599.8 ; v1@1998.79,4588.66 ccw(c1985.35,4575.22) 1985.35,4594.23 ccw(c1985.35,4613.24) v1@1998.79,4599.8 ; v1@2009.93,4588.66 cw(c2023.37,4575.22) 2023.37,4594.23 cw(c2023.37,4613.24) v1@2009.93,4599.8 ; v1@2746.82,4588.66 ccw(c2733.38,4575.22) 2733.38,4594.23 ccw(c2733.38,4613.24) v1@2746.82,4599.8 ; v1@2757.96,4588.66 cw(c2771.4,4575.22) 2771.4,4594.23 cw(c2771.4,4613.24) v1@2757.96,4599.8 ; v1@3494.85,4588.66 ccw(c3481.41,4575.22) 3481.41,4594.23 ccw(c3481.41,4613.24) v1@3494.85,4599.8 ; v1@3505.99,4588.66 cw(c3519.43,4575.22) 3519.43,4594.23 cw(c3519.43,4613.24) v1@3505.99,4599.8 ; v1@4242.89,4588.66 ccw(c4229.44,4575.22) 4229.44,4594.23 ccw(c4229.44,4613.24) v1@4242.89,4599.8 ; v1@4254.02,4588.66 cw(c4267.46,4575.22) 4267.46,4594.23 cw(c4267.46,4613.24) v1@4254.02,4599.8 ; v1@5364.93,4588.66 ccw(c5351.49,4575.22) 5351.49,4594.23 ccw(c5351.49,4613.24) v1@5364.93,4599.8 ; v1@5376.07,4588.66 cw(c5389.51,4575.22) 5389.51,4594.23 cw(c5389.51,4613.24) v1@5376.07,4599.8 ; v1@6112.96,4588.66 ccw(c6099.52,4575.22) 6099.52,4594.23 ccw(c6099.52,4613.24) v1@6112.96,4599.8 ; v1@6124.1,4588.66 cw(c6137.54,4575.22) 6137.54,4594.23 cw(c6137.54,4613.24) v1@6124.1,4599.8 ; v1@6861,4588.66 ccw(c6847.55,4575.22) 6847.55,4594.23 ccw(c6847.55,4613.24) v1@6861,4599.8 ; v1@6872.13,4588.66 cw(c6885.57,4575.22) 6885.57,4594.23 cw(c6885.57,4613.24) v1@6872.13,4599.8 ; v1@7609.03,4588.66 ccw(c7595.59,4575.22) 7595.59,4594.23 ccw(c7595.59,4613.24) v1@7609.03,4599.8 ; v1@7620.16,4588.66 cw(c7633.6,4575.22) 7633.6,4594.23 cw(c7633.6,4613.24) v1@7620.16,4599.8 ; v1@8731.08,4588.66 ccw(c8717.63,4575.22) 8717.63,4594.23 ccw(c8717.63,4613.24) v1@8731.08,4599.8 ; v1@8742.21,4588.66 cw(c8755.65,4575.22) 8755.65,4594.23 cw(c8755.65,4613.24) v1@8742.21,4599.8 ; v1@9479.11,4588.66 ccw(c9465.66,4575.22) 9465.66,4594.23 ccw(c9465.66,4613.24) v1@9479.11,4599.8 ; v1@9490.24,4588.66 cw(c9503.68,4575.22) 9503.68,4594.23 cw(c9503.68,4613.24) v1@9490.24,4599.8 ; v1@10227.14,4588.66 ccw(c10213.7,4575.22) 10213.7,4594.23 ccw(c10213.7,4613.24) v1@10227.14,4599.8 ; v1@10238.27,4588.66 cw(c10251.72,4575.22) 10251.72,4594.23 cw(c10251.72,4613.24) v1@10238.27,4599.8 ; v1@10975.17,4588.66 ccw(c10961.73,4575.22) 10961.73,4594.23 ccw(c10961.73,4613.24) v1@10975.17,4599.8 ; v1@10986.31,4588.66 cw(c10999.75,4575.22) 10999.75,4594.23 cw(c10999.75,4613.24) v1@10986.31,4599.8 ; v1@11927.93,4588.66 ccw(c11914.48,4575.22) 11914.48,4594.23 ccw(c11914.48,4613.24) v1@11927.93,4599.8 ; v1@11939.06,4588.66 cw(c11952.5,4575.22) 11952.5,4594.23 cw(c11952.5,4613.24) v1@11939.06,4599.8 ; 12661.13,4594.23 ccw(c12661.13,4615.2) v1@12675.96,4600.37 ; 12663.9,4594.23 cw(c12663.9,4577.18) v1@12675.96,4589.24 ; v1@12687.09,4589.24 cw(c12699.15,4577.18) 12699.15,4594.23 ; v1@12687.09,4600.37 ccw(c12701.92,4615.2) 12701.92,4594.23 ; v1@13423.99,4588.66 ccw(c13410.55,4575.22) 13410.55,4594.23 ccw(c13410.55,4613.24) v1@13423.99,4599.8
  Bottom Layer w7.87: LED1.R@434.67,4476.58 491.73,4476.58 508.3,4493.14 v1(508.3,4594.23) ; v1@502.73,4588.66 cw(c489.29,4575.22) 508.3,4575.22 cw(c527.31,4575.22) v1@513.86,4588.66 ; LED2.R@1930.73,4476.58 1987.79,4476.58 2004.36,4493.15 v1(2004.36,4594.23) ; v1@1998.79,4588.66 cw(c1985.35,4575.22) 2004.36,4575.22 cw(c2023.37,4575.22) v1@2009.93,4588.66 ; LED3.R@2678.76,4476.58 2735.82,4476.58 2752.39,4493.15 v1(2752.39,4594.23) ; v1@2746.82,4588.66 cw(c2733.38,4575.22) 2752.39,4575.22 cw(c2771.4,4575.22) v1@2757.96,4588.66 ; LED4.R@3426.8,4476.58 3483.85,4476.58 3500.42,4493.14 v1(3500.42,4594.23) ; v1@3494.85,4588.66 cw(c3481.41,4575.22) 3500.42,4575.22 cw(c3519.43,4575.22) v1@3505.99,4588.66 ; LED5.R@4174.83,4476.58 4231.89,4476.58 4248.45,4493.15 v1(4248.45,4594.23) ; v1@4242.89,4588.66 cw(c4229.44,4575.22) 4248.45,4575.22 cw(c4267.46,4575.22) v1@4254.02,4588.66 ; LED6.R@5296.87,4476.58 5353.93,4476.58 5370.5,4493.15 v1(5370.5,4594.23) ; v1@5364.93,4588.66 cw(c5351.49,4575.22) 5370.5,4575.22 cw(c5389.51,4575.22) v1@5376.07,4588.66 ; LED7.R@6044.91,4476.58 6101.96,4476.58 6118.53,4493.15 v1(6118.53,4594.23) ; v1@6112.96,4588.66 cw(c6099.52,4575.22) 6118.53,4575.22 cw(c6137.54,4575.22) v1@6124.1,4588.66 ; LED8.R@6792.94,4476.58 6850,4476.58 6866.56,4493.15 v1(6866.56,4594.23) ; v1@6861,4588.66 cw(c6847.55,4575.22) 6866.56,4575.22 cw(c6885.57,4575.22) v1@6872.13,4588.66 ; LED9.R@7540.97,4476.58 7598.03,4476.58 7614.6,4493.15 v1(7614.6,4594.23) ; v1@7609.03,4588.66 cw(c7595.59,4575.22) 7614.6,4575.22 cw(c7633.6,4575.22) v1@7620.16,4588.66 ; LED10.R@8663.02,4476.58 8720.08,4476.58 8736.64,4493.14 v1(8736.64,4594.23) ; v1@8731.08,4588.66 cw(c8717.63,4575.22) 8736.64,4575.22 cw(c8755.65,4575.22) v1@8742.21,4588.66 ; LED11.R@9411.05,4476.58 9468.11,4476.58 9484.67,4493.15 v1(9484.67,4594.23) ; v1@9479.11,4588.66 cw(c9465.66,4575.22) 9484.67,4575.22 cw(c9503.68,4575.22) v1@9490.24,4588.66 ; LED12.R@10159.08,4476.58 10216.14,4476.58 10232.71,4493.14 v1(10232.71,4594.23) ; v1@10227.14,4588.66 cw(c10213.7,4575.22) 10232.71,4575.22 cw(c10251.72,4575.22) v1@10238.27,4588.66 ; LED13.R@10907.11,4476.58 10964.17,4476.58 10980.74,4493.14 v1(10980.74,4594.23) ; v1@10975.17,4588.66 cw(c10961.73,4575.22) 10980.74,4575.22 cw(c10999.75,4575.22) v1@10986.31,4588.66 ; LED14.R@11859.87,4476.58 11916.93,4476.58 11933.49,4493.14 v1(11933.49,4594.23) ; v1@11927.93,4588.66 cw(c11914.48,4575.22) 11933.49,4575.22 cw(c11952.5,4575.22) v1@11939.06,4588.66 ; RR1.2@12478.94,2165.61 12478.94,2208.4 12493,2222.45 12650.58,2222.45 12758.71,2330.58 12758.71,4399.39 12681.52,4476.58 ; LED15.R@12607.9,4476.58 12681.52,4476.58 ; v1@12675.96,4589.24 cw(c12662.52,4575.79) 12681.52,4575.79 cw(c12700.53,4575.79) v1@12687.09,4589.24 ; v1(12681.52,4594.8) 12681.52,4476.58 ; LED16.R@13355.93,4476.58 13419.42,4476.58 13429.56,4486.72 ; v1@13423.99,4588.66 cw(c13410.55,4575.22) 13429.56,4575.22 cw(c13448.57,4575.22) v1@13435.12,4588.66 ; v1(13429.56,4594.23) 13429.56,4486.72 ; NUM.2@14213.07,4307.08 14213.07,4486.08 ; CAPS.2@14803.62,4307.08 14803.62,4486.37 ; SCR.2@15394.17,4307.08 15394.17,4485.87 ; WIN.2@15984.72,4307.08 15984.72,4463.47 15961.48,4486.72 13429.56,4486.72
RED1: LED17.R LED18.R LED19.R LED20.R LED21.R LED22.R LED23.R LED24.R LED25.R LED26.R LED27.R LED28.R LED29.R LED30.R LED31.R LED32.R LED33.R LED34.R LED35.R LED36.R LED37.R RR4.2 | length 24573.6
  Top Layer w7.87: v1(497.16,3616.32) 516.04,3635.19 v1@13628.49,3635.19 ; v1@497.16,3624.19 ccw(c497.16,3643.2) 510.6,3629.76 ccw(c524.04,3616.32) v1@505.03,3616.32 ; 1214.51,3635.19 cw(c1214.51,3602.63) v1@1237.54,3625.65 ; v1@1248.67,3625.65 cw(c1271.7,3602.63) 1271.7,3635.19 ; 1982.12,3635.19 cw(c1982.12,3606.67) v1@2002.29,3626.84 ; 1995.58,3635.19 ccw(c1995.58,3644.69) v1@2002.29,3637.97 ; v1@2013.43,3626.84 cw(c2033.59,3606.67) 2033.59,3635.19 ; v1@2013.43,3637.97 ccw(c2020.14,3644.69) 2020.14,3635.19 ; 2718.84,3635.19 cw(c2718.84,3600.46) v1@2743.4,3625.02 ; 2737.85,3635.19 cw(c2737.85,3619.47) v1(2748.97,3630.59) cw(c2760.09,3619.47) 2760.09,3635.19 ; v1@2754.54,3625.02 cw(c2779.1,3600.46) 2779.1,3635.19 ; 3461.91,3635.19 cw(c3461.91,3600.58) v1@3486.38,3625.05 ; 3480.92,3635.19 cw(c3480.92,3619.59) v1(3491.95,3630.62) cw(c3502.98,3619.59) 3502.98,3635.19 ; v1@3497.52,3625.05 cw(c3521.99,3600.58) 3521.99,3635.19 ; 4214.42,3635.19 cw(c4214.42,3602.45) v1@4237.57,3625.6 ; v1@4248.71,3625.6 cw(c4271.86,3602.45) 4271.86,3635.19 ; 4960.85,3635.19 cw(c4960.85,3601.4) v1@4984.74,3625.3 ; v1@4995.88,3625.3 cw(c5019.77,3601.4) 5019.77,3635.19 ; 5716.08,3635.19 cw(c5716.08,3606.02) v1@5736.7,3626.65 ; 5730.45,3635.19 ccw(c5730.45,3644.04) v1@5736.7,3637.78 ; v1@5747.84,3626.65 cw(c5768.47,3606.02) 5768.47,3635.19 ; v1@5747.84,3637.78 ccw(c5754.1,3644.04) 5754.1,3635.19 ; 6462.96,3635.19 cw(c6462.96,3601.94) v1@6486.47,3625.45 ; v1@6497.61,3625.45 cw(c6521.12,3601.94) 6521.12,3635.19 ; 7213.07,3635.19 cw(c7213.07,3603.03) v1@7235.81,3625.77 ; v1@7246.94,3625.77 cw(c7269.69,3603.03) 7269.69,3635.19 ; 7947.15,3635.19 cw(c7947.15,3603.88) v1@7969.29,3626.02 ; v1@7980.42,3626.02 cw(c8002.57,3603.88) 8002.57,3635.19 ; 8710.37,3635.19 cw(c8710.37,3605.22) v1@8731.56,3626.41 ; v1@8742.7,3626.41 cw(c8763.9,3605.22) 8763.9,3635.19 ; 9462.41,3635.19 cw(c9462.41,3608.45) v1@9481.32,3627.36 ; 9473.34,3635.19 ccw(c9473.34,3646.47) v1@9481.32,3638.5 ; v1@9492.46,3627.36 cw(c9511.36,3608.45) 9511.36,3635.19 ; v1@9492.46,3638.5 ccw(c9500.43,3646.47) 9500.43,3635.19 ; 10576.87,3635.19 cw(c10576.87,3608.11) v1@10596.02,3627.26 ; 10588.28,3635.19 ccw(c10588.28,3646.13) v1@10596.02,3638.39 ; v1@10607.15,3627.26 cw(c10626.3,3608.11) 10626.3,3635.19 ; v1@10607.15,3638.39 ccw(c10614.88,3646.13) 10614.88,3635.19 ; 11885.44,3635.19 cw(c11885.44,3603.47) v1@11907.87,3625.9 ; v1@11919,3625.9 cw(c11941.43,3603.47) 11941.43,3635.19 ; 12638.92,3635.19 cw(c12638.92,3604.98) v1@12660.28,3626.34 ; v1@12671.41,3626.34 cw(c12692.78,3604.98) 12692.78,3635.19 ; 13393.96,3635.19 cw(c13393.96,3606.25) v1@13414.42,3626.71 ; 13408,3635.19 ccw(c13408,3644.27) v1@13414.42,3637.85 ; v1@13425.56,3626.71 cw(c13446.02,3606.25) 13446.02,3635.19 ; v1@13425.56,3637.85 ccw(c13431.98,3644.27) 13431.98,3635.19 ; 13601.69,3635.19 cw(c13601.69,3605.16) v1@13622.92,3626.4 ; v1(13628.49,3631.96) 13726.2,3631.96 13729.42,3635.19 v1(16584.61,3635.19) ; v1@13634.06,3626.4 cw(c13647.5,3612.95) 13647.5,3631.96 cw(c13647.5,3650.97) v1@13634.06,3637.53 ; 14332.16,3635.19 cw(c14332.16,3602.24) v1@14355.46,3625.54 ; v1@14366.6,3625.54 cw(c14389.9,3602.24) 14389.9,3635.19 ; 15105.56,3635.19 cw(c15105.56,3607.14) v1@15125.4,3626.97 ; 15118.35,3635.19 ccw(c15118.35,3645.15) v1@15125.4,3638.11 ; v1@15136.53,3626.97 cw(c15156.37,3607.14) 15156.37,3635.19 ; v1@15136.53,3638.11 ccw(c15143.58,3645.15) 15143.58,3635.19 ; 15839.03,3635.19 cw(c15839.03,3609.79) v1@15856.99,3627.75 ; 15848.07,3635.19 ccw(c15848.07,3647.81) v1@15856.99,3638.89 ; v1@15868.12,3627.75 cw(c15886.09,3609.79) 15886.09,3635.19 ; v1@15868.12,3638.89 ccw(c15877.05,3647.81) 15877.05,3635.19 ; v1@16579.04,3629.62 ccw(c16565.6,3616.18) 16565.6,3635.19 ccw(c16565.6,3654.2) v1@16579.04,3640.76
  Bottom Layer w7.87: LED17.R@435.65,3527.76 489.1,3527.76 497.16,3535.82 v1(497.16,3616.32) ; LED17.R@459.18,3518.01 cw(c482.7,3494.49) 482.7,3527.76 cw(c482.7,3561.02) LED17.R@459.18,3537.5 ; v1@491.59,3610.75 cw(c478.15,3597.31) 497.16,3597.31 cw(c516.17,3597.31) v1@502.73,3610.75 ; LED18.R@1183.69,3527.76 1232.18,3527.76 1243.1,3538.68 v1(1243.1,3631.22) ; LED18.R@1207.21,3518.01 cw(c1230.73,3494.49) 1230.73,3527.76 cw(c1230.73,3561.02) LED18.R@1207.21,3537.5 ; v1@1237.54,3625.65 cw(c1224.09,3612.21) 1243.1,3612.21 cw(c1262.11,3612.21) v1@1248.67,3625.65 ; LED19.R@1931.72,3527.76 1990.94,3527.76 2007.86,3544.68 v1(2007.86,3632.4) ; LED19.R@1955.24,3518.01 cw(c1978.76,3494.49) 1978.76,3527.76 cw(c1978.76,3561.02) LED19.R@1955.24,3537.5 ; v1@2002.29,3626.84 cw(c1988.85,3613.4) 2007.86,3613.4 cw(c2026.87,3613.4) v1@2013.43,3626.84 ; LED20.R@2679.75,3527.76 2733.24,3527.76 2748.97,3543.49 v1(2748.97,3630.59) ; LED20.R@2703.27,3518.01 cw(c2726.79,3494.49) 2726.79,3527.76 cw(c2726.79,3561.02) LED20.R@2703.27,3537.5 ; v1@2743.4,3625.02 cw(c2729.96,3611.58) 2748.97,3611.58 cw(c2767.98,3611.58) v1@2754.54,3625.02 ; LED21.R@3427.78,3527.76 3474.58,3527.76 3491.95,3545.13 v1(3491.95,3630.62) ; LED21.R@3451.35,3518.07 cw(c3474.58,3495.09) 3474.58,3527.76 cw(c3474.58,3560.43) LED21.R@3451.35,3537.45 ; v1@3486.38,3625.05 cw(c3472.94,3611.61) 3491.95,3611.61 cw(c3510.96,3611.61) v1@3497.52,3625.05 ; LED22.R@4175.81,3527.76 4233.26,3527.76 4243.14,3537.64 v1(4243.14,3631.17) ; LED22.R@4199.33,3518.01 cw(c4222.86,3494.49) 4222.86,3527.76 cw(c4222.86,3561.02) LED22.R@4199.33,3537.5 ; v1@4237.57,3625.6 cw(c4224.13,3612.16) 4243.14,3612.16 cw(c4262.15,3612.16) v1@4248.71,3625.6 ; LED23.R@4923.84,3527.76 4980.75,3527.76 4990.31,3537.31 v1(4990.31,3630.86) ; LED23.R@4947.37,3518.01 cw(c4970.89,3494.49) 4970.89,3527.76 cw(c4970.89,3561.02) LED23.R@4947.37,3537.5 ; v1@4984.74,3625.3 cw(c4971.3,3611.85) 4990.31,3611.85 cw(c5009.32,3611.85) v1@4995.88,3625.3 ; LED24.R@5671.87,3527.76 5731.17,3527.76 5742.27,3538.86 v1(5742.27,3632.21) ; LED24.R@5695.4,3518.01 cw(c5718.92,3494.49) 5718.92,3527.76 cw(c5718.92,3561.02) LED24.R@5695.4,3537.5 ; v1@5736.7,3626.65 cw(c5723.26,3613.21) 5742.27,3613.21 cw(c5761.28,3613.21) v1@5747.84,3626.65 ; LED25.R@6419.91,3527.76 6476.67,3527.76 6492.04,3543.12 v1(6492.04,3631.02) ; LED25.R@6443.43,3518.01 cw(c6466.95,3494.49) 6466.95,3527.76 cw(c6466.95,3561.02) LED25.R@6443.43,3537.5 ; v1@6486.47,3625.45 cw(c6473.03,3612.01) 6492.04,3612.01 cw(c6511.05,3612.01) v1@6497.61,3625.45 ; LED26.R@7167.94,3527.76 7230,3527.76 7241.38,3539.14 v1(7241.38,3631.34) ; LED26.R@7191.46,3518.01 cw(c7214.98,3494.49) 7214.98,3527.76 cw(c7214.98,3561.02) LED26.R@7191.46,3537.5 ; v1@7235.81,3625.77 cw(c7222.37,3612.33) 7241.38,3612.33 cw(c7260.39,3612.33) v1@7246.94,3625.77 ; LED27.R@7915.97,3527.76 7959.69,3527.76 ; LED27.R@7940.21,3518.79 cw(c7959.69,3502.11) 7959.69,3527.76 ; LED27.R@7940.21,3536.72 ccw(c7959.69,3553.4) 7959.69,3527.76 ; v1@7969.29,3626.02 cw(c7955.85,3612.58) 7974.86,3612.58 cw(c7993.87,3612.58) v1@7980.42,3626.02 ; v1(7974.86,3631.59) 7974.86,3542.92 7959.69,3527.76 ; LED28.R@8664,3527.76 8725.5,3527.76 8737.13,3539.39 v1(8737.13,3631.98) ; LED28.R@8687.52,3518.01 cw(c8711.05,3494.49) 8711.05,3527.76 cw(c8711.05,3561.02) LED28.R@8687.52,3537.5 ; v1@8731.56,3626.41 cw(c8718.12,3612.97) 8737.13,3612.97 cw(c8756.14,3612.97) v1@8742.7,3626.41 ; LED29.R@9412.03,3527.76 9471.89,3527.76 9486.89,3542.75 v1(9486.89,3632.93) ; LED29.R@9435.55,3518.01 cw(c9459.08,3494.49) 9459.08,3527.76 cw(c9459.08,3561.02) LED29.R@9435.55,3537.5 ; v1@9481.32,3627.36 cw(c9467.88,3613.92) 9486.89,3613.92 cw(c9505.9,3613.92) v1@9492.46,3627.36 ; LED30.R@10534.08,3527.76 10588.44,3527.76 10601.58,3540.9 v1(10601.58,3632.83) ; LED30.R@10557.6,3518.01 cw(c10581.12,3494.49) 10581.12,3527.76 cw(c10581.12,3561.02) LED30.R@10557.6,3537.5 ; v1@10596.02,3627.26 cw(c10582.57,3613.82) 10601.58,3613.82 cw(c10620.59,3613.82) v1@10607.15,3627.26 ; LED31.R@11852.98,3527.76 11903.52,3527.76 11913.44,3537.67 v1(11913.44,3631.47) ; LED31.R@11876.5,3518.01 cw(c11900.02,3494.49) 11900.02,3527.76 cw(c11900.02,3561.02) LED31.R@11876.5,3537.5 ; v1@11907.87,3625.9 cw(c11894.43,3612.46) 11913.44,3612.46 cw(c11932.45,3612.46) v1@11919,3625.9 ; LED32.R@12601.01,3527.76 12645.5,3527.76 ; LED32.R@12625.08,3518.6 cw(c12645.5,3500.42) 12645.5,3527.76 ; LED32.R@12625.08,3536.92 ccw(c12645.5,3555.09) 12645.5,3527.76 ; v1@12660.28,3626.34 cw(c12646.84,3612.9) 12665.85,3612.9 cw(c12684.86,3612.9) v1@12671.41,3626.34 ; v1(12665.85,3631.91) 12665.85,3548.1 12645.5,3527.76 ; RR4.2@12872.69,2165.61 12872.69,2206.73 12901.01,2235.05 13404.61,2235.05 13499.68,2330.13 13499.68,2577.2 13560.71,2638.23 13560.71,3080.02 13652.24,3171.55 13652.24,3611.57 v1@13628.62,3635.19 ; LED33.R@13349.04,3527.76 13407.01,3527.76 13419.99,3540.74 v1(13419.99,3632.28) ; LED33.R@13372.56,3518.01 cw(c13396.09,3494.49) 13396.09,3527.76 cw(c13396.09,3561.02) LED33.R@13372.56,3537.5 ; v1@13414.42,3626.71 cw(c13400.98,3613.27) 13419.99,3613.27 cw(c13439,3613.27) v1@13425.56,3626.71 ; v1@13628.49,3624.09 cw(c13628.49,3596.98) 13647.66,3616.15 ; v1@13636.37,3631.96 ccw(c13647.27,3631.96) 13639.56,3624.25 ; LED34.R@14299.83,3527.76 14353.06,3527.76 14361.03,3535.73 v1(14361.03,3631.11) ; LED34.R@14323.35,3518.01 cw(c14346.87,3494.49) 14346.87,3527.76 cw(c14346.87,3561.02) LED34.R@14323.35,3537.5 ; v1@14355.46,3625.54 cw(c14342.02,3612.1) 14361.03,3612.1 cw(c14380.04,3612.1) v1@14366.6,3625.54 ; LED35.R@15047.86,3527.76 15113.55,3527.76 15130.97,3545.17 v1(15130.97,3632.54) ; LED35.R@15071.38,3518.01 cw(c15094.9,3494.49) 15094.9,3527.76 cw(c15094.9,3561.02) LED35.R@15071.38,3537.5 ; v1@15125.4,3626.97 cw(c15111.96,3613.53) 15130.97,3613.53 cw(c15149.98,3613.53) v1@15136.53,3626.97 ; LED36.R@15795.89,3527.76 15847.68,3527.76 15862.41,3542.48 v1@15862.41,3635.22 ; LED36.R@15819.41,3518.01 cw(c15842.94,3494.49) 15842.94,3527.76 cw(c15842.94,3561.02) LED36.R@15819.41,3537.5 ; v1@15856.99,3627.75 cw(c15843.91,3614.68) 15862.41,3614.68 ; 15862.41,3613.94 cw(c15881.93,3613.94) v1@15868.12,3627.75 ; LED37.R@16543.92,3527.76 16595.36,3527.76 16608.22,3540.62 16608.22,3611.58 v1(16584.61,3635.19) ; LED37.R@16567.44,3518.01 cw(c16590.97,3494.49) 16590.97,3527.76 cw(c16590.97,3561.02) LED37.R@16567.44,3537.5 ; v1@16584.61,3627.32 cw(c16584.61,3608.31) 16598.05,3621.75 cw(c16611.49,3635.19) v1@16592.48,3635.19
  other v1: 15862.56,3633.32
